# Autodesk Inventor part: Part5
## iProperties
Shininess: 77.0
Length Units: 11269
Angle Units: 11279
Time Units: 11290
Mass Units: 11283
Length Display Precision: 3
Angle Display Precision: 2
Created: 2002-01
Part Number: Part5
Document SubType Name: Modeling
Designer: ***
Density: 1 g/cm^3
Density: 0.0
Volumn: 0.0
Area: 0.0
PropertySet Name: Model Information
Control State: 0
Master: False
Checked Out: False
Author: ***
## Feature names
1. Extrusion1
2. Extrusion2
